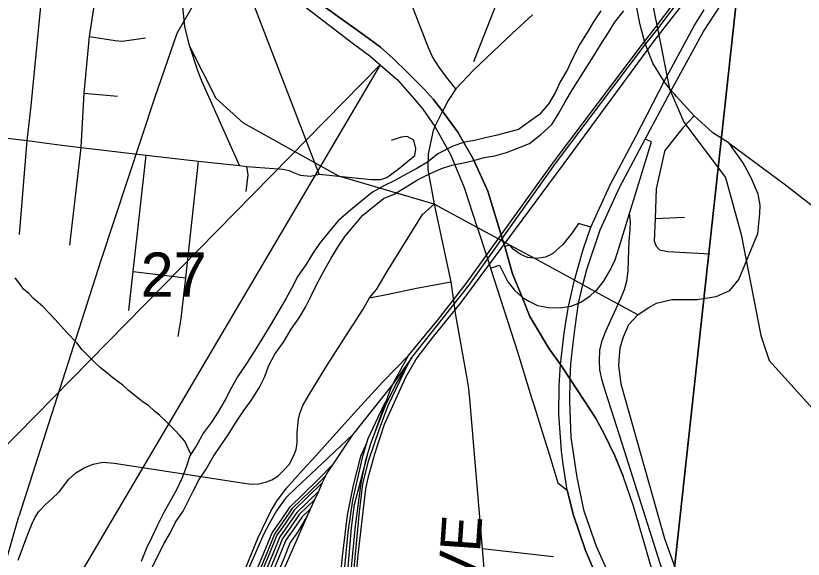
# Model space of a CAD drawing. Extents: x -8.2 to 38.5, y -0.1 to 21.9.
# Drawn here: x 5.137 to 5.881, y 17.376 to 17.89 of the extents above; entities that cross this region are included whole.
import ezdxf

# ---------------------------------------------------------------- set-up
doc = ezdxf.new("R2010")
doc.units = 0
for name, color, linetype in [('GM_X_Adjacent_County', 7, 'Continuous'), ('GM_X_Adjacent_County_Text', 7, 'Continuous'), ('GM_X_Airport_Location_Class_3', 7, 'Continuous'), ('GM_X_County_Road_Text', 7, 'Continuous'), ('GM_X_Interstate_Location', 7, 'Continuous'), ('GM_X_Major_Lake', 7, 'Continuous'), ('GM_X_Minor_River', 7, 'Continuous'), ('GM_X_State_Location', 7, 'Continuous'), ('GM_X_Township_Subdivision_Text', 7, 'Continuous'), ('GM_X_Township_Text', 7, 'Continuous'), ('GM_X_US_Location', 7, 'Continuous')]:
    doc.layers.add(name, color=color, linetype=linetype)

msp = doc.modelspace()

# ---------------------------------------------------------------- linework, layer by layer
at = {"layer": 'GM_X_Adjacent_County'}
msp.add_lwpolyline([(5.03564, 17.38985), (5.48132, 17.8434), (5.03564, 17.08755)], close=True, dxfattribs=at)
at = {"layer": 'GM_X_Adjacent_County_Text'}
msp.add_lwpolyline([(4.75441, 17.38985), (4.83948, 18.19258), (5.83799, 18.09248), (5.7325, 17.12325), (5.03564, 17.19219)], dxfattribs=at)
msp.add_lwpolyline([(6.85894, 17.99642), (6.75364, 16.98553), (5.7325, 17.12325), (5.83799, 18.09248)], close=True, dxfattribs=at)
at = {"layer": 'GM_X_Airport_Location_Class_3'}
for p, q in [((5.79156, 17.78276), (5.77757, 17.79539)), ((5.58243, 17.66065), (5.58539, 17.65149))]:
    msp.add_line(p, q, dxfattribs=at)
for points in [[(5.59883, 17.67204), (5.59746, 17.67656), (5.58298, 17.72409), (5.58161, 17.72708), (5.56894, 17.75479), (5.55447, 17.78002), (5.54008, 17.79971), (5.53161, 17.81077), (5.52289, 17.82015), (5.50709, 17.83638), (5.49339, 17.84965), (5.48154, 17.86018), (5.46608, 17.87148), (5.41629, 17.90733), (5.40533, 17.91556), (5.33437, 17.96919), (5.24763, 18.034), (5.20069, 18.07549)], [(5.7594, 17.81549), (5.75592, 17.81917), (5.74934, 17.82772), (5.7386, 17.84505), (5.73114, 17.86457), (5.72675, 17.88124), (5.72302, 17.90054), (5.71691, 17.97934), (5.70735, 18.05462), (5.70717, 18.05558)], [(5.29632, 17.98651), (5.32538, 17.96348), (5.39662, 17.90939), (5.45588, 17.86325), (5.47134, 17.85196), (5.48132, 17.8434), (5.488, 17.83765)], [(5.488, 17.83765), (5.49765, 17.82934), (5.51302, 17.8116), (5.52161, 17.80167), (5.53266, 17.78541), (5.54745, 17.75874), (5.56039, 17.7276), (5.57279, 17.68998), (5.5734, 17.68815)], [(5.77757, 17.79539), (5.76079, 17.81401), (5.7594, 17.81549)], [(5.7613, 17.36432), (5.74999, 17.39563), (5.70861, 17.5419), (5.70667, 17.55968), (5.70778, 17.57605), (5.71084, 17.58661), (5.71583, 17.59828), (5.72445, 17.60743), (5.73416, 17.61382), (5.74222, 17.61826), (5.75671, 17.62195), (5.78054, 17.62187), (5.79831, 17.62465), (5.81136, 17.63049), (5.81997, 17.64076), (5.8377, 17.68413), (5.83983, 17.70304), (5.84, 17.71109), (5.83819, 17.72128), (5.83161, 17.73674), (5.82355, 17.75137), (5.81077, 17.76939), (5.79545, 17.77926), (5.79156, 17.78276)], [(5.5734, 17.68815), (5.58035, 17.66706), (5.58243, 17.66065)], [(5.71065, 17.45498), (5.70279, 17.47416), (5.6926, 17.49495), (5.68444, 17.51017), (5.67396, 17.52647), (5.66069, 17.54665), (5.65141, 17.56047), (5.64067, 17.57538), (5.62246, 17.60587), (5.61538, 17.62419), (5.60624, 17.6462), (5.59883, 17.67204)], [(5.58539, 17.65149), (5.61084, 17.57231), (5.62422, 17.5291), (5.62654, 17.52152)], [(5.62654, 17.52152), (5.63003, 17.51013), (5.64231, 17.47065), (5.64889, 17.44872), (5.65771, 17.44158)], [(5.86706, 17.12546), (5.85953, 17.13966), (5.85133, 17.15452), (5.83903, 17.17436), (5.83173, 17.18557), (5.81998, 17.20364), (5.80911, 17.22051), (5.7981, 17.23732), (5.78865, 17.25173), (5.78168, 17.26126), (5.77559, 17.27082), (5.76723, 17.28754), (5.75788, 17.30456), (5.7488, 17.32855), (5.73932, 17.36131), (5.73052, 17.39223), (5.72048, 17.42654), (5.71065, 17.45498)], [(5.65771, 17.44158), (5.66359, 17.41823), (5.67499, 17.38468), (5.68513, 17.36098), (5.70146, 17.32687), (5.71759, 17.29913), (5.73996, 17.26601), (5.78093, 17.20921), (5.80478, 17.17521), (5.82506, 17.14461), (5.83932, 17.11884), (5.85193, 17.09208), (5.86158, 17.0684)]]:
    msp.add_lwpolyline(points, dxfattribs=at)
at = {"layer": 'GM_X_Interstate_Location'}
for points in [[(5.58539, 17.65149), (5.59373, 17.65434), (5.6018, 17.63841), (5.60814, 17.63079), (5.61538, 17.62419), (5.62166, 17.62017), (5.62981, 17.61611), (5.64024, 17.61435), (5.65129, 17.61397), (5.65899, 17.61519), (5.66156, 17.6156), (5.6685, 17.61846), (5.67073, 17.61938), (5.6794, 17.62527), (5.68402, 17.62944), (5.68601, 17.63123), (5.69206, 17.6387), (5.69743, 17.64792), (5.70268, 17.65824), (5.7071, 17.67225), (5.71648, 17.70292), (5.72408, 17.72777), (5.73728, 17.77065), (5.73131, 17.77337)], [(5.74791, 17.36544), (5.70961, 17.48582), (5.69383, 17.53501), (5.69094, 17.54527), (5.6887, 17.55526), (5.68817, 17.56394), (5.6887, 17.57394), (5.69081, 17.58301), (5.69423, 17.59196), (5.70882, 17.62379), (5.71185, 17.63128), (5.71422, 17.63917), (5.7154, 17.64878), (5.71579, 17.65956), (5.71645, 17.67679), (5.71711, 17.68771), (5.7175, 17.69586), (5.71648, 17.70292)], [(5.68016, 17.69017), (5.66845, 17.69361), (5.66261, 17.68482), (5.65366, 17.67367), (5.64402, 17.66511), (5.63719, 17.66193), (5.62885, 17.66047), (5.62653, 17.66074), (5.62016, 17.66146), (5.61324, 17.66456), (5.60684, 17.66929), (5.60348, 17.67329), (5.59883, 17.67204)]]:
    msp.add_lwpolyline(points, dxfattribs=at)
at = {"layer": 'GM_X_Minor_River'}
for points in [[(5.6895, 17.89451), (5.68276, 17.88406), (5.67679, 17.87398), (5.66966, 17.86316), (5.66323, 17.85005), (5.65799, 17.83918), (5.65122, 17.82759), (5.64677, 17.81784), (5.64041, 17.80701), (5.63177, 17.79661), (5.62172, 17.78967), (5.61165, 17.78236), (5.59027, 17.77687), (5.58072, 17.77447), (5.57041, 17.7721), (5.56089, 17.77046), (5.54978, 17.76659), (5.53555, 17.75938), (5.52585, 17.75168), (5.51582, 17.7455), (5.50581, 17.74008), (5.49503, 17.7343), (5.48465, 17.72927), (5.47386, 17.72311), (5.46223, 17.71393), (5.45136, 17.70474), (5.44164, 17.69627), (5.4334, 17.68625), (5.42397, 17.67473), (5.41726, 17.66505), (5.41089, 17.65459), (5.40339, 17.64379), (5.39737, 17.63218), (5.39217, 17.62245), (5.3858, 17.61161), (5.37824, 17.59891), (5.37188, 17.58845), (5.36433, 17.57613), (5.3556, 17.56232), (5.3465, 17.5489), (5.34011, 17.53731), (5.3349, 17.5272), (5.32812, 17.51561), (5.32178, 17.50591), (5.3143, 17.49587), (5.3079, 17.48389), (5.30156, 17.47419), (5.29825, 17.46441), (5.29375, 17.45276), (5.28851, 17.44152), (5.28291, 17.43142), (5.27732, 17.42132), (5.2709, 17.40859), (5.26565, 17.39734), (5.26043, 17.38685), (5.25553, 17.37446)], [(5.26599, 17.36885), (5.27161, 17.38009), (5.27685, 17.39096), (5.28282, 17.40105), (5.28804, 17.41153), (5.29516, 17.42197), (5.30481, 17.44145), (5.31041, 17.45193), (5.31675, 17.46163), (5.32352, 17.47321), (5.33065, 17.48403), (5.33816, 17.49483), (5.34491, 17.50566), (5.35243, 17.51684), (5.35952, 17.52652), (5.36706, 17.53847), (5.37229, 17.54895), (5.37559, 17.55873), (5.38161, 17.57034), (5.38988, 17.5815), (5.39705, 17.59384), (5.40456, 17.60464), (5.41053, 17.61473), (5.41614, 17.62521), (5.42177, 17.63683), (5.42818, 17.64918), (5.43495, 17.66076), (5.44132, 17.67122), (5.44805, 17.68167), (5.45668, 17.69168), (5.46453, 17.70134), (5.47462, 17.70942), (5.48431, 17.71713), (5.49429, 17.72141), (5.5047, 17.72758), (5.51628, 17.73485), (5.52705, 17.74025), (5.53896, 17.74562), (5.5489, 17.74877), (5.55844, 17.75078), (5.56835, 17.75279), (5.57944, 17.7559), (5.58934, 17.75753), (5.60043, 17.76064), (5.61193, 17.76526), (5.62228, 17.76915), (5.63275, 17.7776), (5.64326, 17.78718), (5.65001, 17.79801), (5.65599, 17.80848), (5.66276, 17.82006), (5.6695, 17.83051), (5.67704, 17.84245), (5.683, 17.85216), (5.68976, 17.86337), (5.69689, 17.87418), (5.70285, 17.88389), (5.71112, 17.89468)], [(5.30247, 17.47559), (5.29676, 17.48809), (5.29233, 17.49316), (5.28678, 17.49903), (5.27864, 17.50726), (5.27307, 17.51237), (5.26824, 17.51631), (5.2623, 17.5218), (5.25744, 17.52499), (5.2526, 17.52855), (5.24367, 17.53603), (5.2381, 17.54076), (5.23363, 17.54431), (5.22878, 17.54787), (5.22284, 17.55299), (5.21725, 17.55734), (5.21168, 17.56244), (5.20465, 17.5695), (5.19983, 17.5742), (5.19469, 17.58082), (5.18545, 17.5906), (5.17438, 17.60309), (5.16254, 17.61523), (5.15399, 17.6227), (5.14956, 17.6274), (5.14435, 17.63173), (5.14106, 17.63677), (5.13665, 17.64223)]]:
    msp.add_lwpolyline(points, dxfattribs=at)
at = {"layer": 'GM_X_State_Location'}
msp.add_line((5.58243, 17.66065), (5.58539, 17.65149), dxfattribs=at)
for points in [[(5.75024, 17.8086), (5.75592, 17.81917), (5.78641, 17.87488), (5.80242, 17.89944), (5.81712, 17.91896), (5.83159, 17.93563), (5.85287, 17.95603), (5.87655, 17.97467), (5.90112, 17.99134), (5.93014, 18.00732), (5.95069, 18.01393), (5.97986, 18.02205), (6.02021, 18.03038), (6.07943, 18.03937), (6.11343, 18.04551), (6.15049, 18.05582), (6.18339, 18.06635), (6.21761, 18.08017), (6.49366, 18.20681)], [(5.20069, 18.07549), (5.24763, 18.034), (5.33437, 17.96919), (5.40533, 17.91556), (5.41629, 17.90733), (5.46608, 17.87148), (5.48154, 17.86018), (5.49339, 17.84965), (5.50709, 17.83638), (5.52289, 17.82015), (5.53161, 17.81077), (5.54008, 17.79971), (5.55447, 17.78002), (5.56894, 17.75479), (5.58161, 17.72708), (5.58298, 17.72409), (5.59746, 17.67656), (5.59883, 17.67204)], [(5.29632, 17.98651), (5.32538, 17.96348), (5.39662, 17.90939), (5.45588, 17.86325), (5.47134, 17.85196), (5.48132, 17.8434), (5.488, 17.83765)], [(5.65771, 17.44158), (5.65351, 17.46844), (5.6524, 17.47899), (5.64999, 17.5132), (5.65021, 17.54018), (5.65141, 17.56047), (5.65459, 17.58756), (5.6564, 17.60038), (5.65899, 17.61519), (5.66459, 17.64002), (5.67275, 17.66899), (5.68016, 17.69017), (5.69836, 17.73031), (5.72244, 17.77597), (5.74934, 17.82772), (5.77758, 17.88024), (5.78712, 17.89559)], [(5.488, 17.83765), (5.49765, 17.82934), (5.51302, 17.8116), (5.52161, 17.80167), (5.53266, 17.78541), (5.54745, 17.75874), (5.56039, 17.7276), (5.57279, 17.68998), (5.5734, 17.68815)], [(5.66971, 17.44155), (5.66771, 17.45087), (5.66709, 17.45376), (5.66161, 17.49193), (5.6603, 17.52549), (5.66069, 17.54665), (5.66106, 17.56113), (5.66337, 17.58054), (5.6654, 17.59564), (5.6685, 17.61846), (5.6727, 17.6356), (5.67631, 17.65028), (5.68903, 17.68757), (5.70723, 17.72771), (5.73131, 17.77337), (5.75024, 17.8086)], [(5.5734, 17.68815), (5.58035, 17.66706), (5.58243, 17.66065)], [(5.59883, 17.67204), (5.60624, 17.6462), (5.61538, 17.62419), (5.62246, 17.60587), (5.64067, 17.57538), (5.65141, 17.56047), (5.66069, 17.54665), (5.67396, 17.52647), (5.68444, 17.51017), (5.6926, 17.49495), (5.70279, 17.47416), (5.71065, 17.45498)], [(5.58539, 17.65149), (5.61084, 17.57231), (5.62422, 17.5291), (5.62654, 17.52152)], [(5.62654, 17.52152), (5.63003, 17.51013), (5.64231, 17.47065), (5.64889, 17.44872), (5.65771, 17.44158)], [(5.86158, 17.0684), (5.85193, 17.09208), (5.83932, 17.11884), (5.82506, 17.14461), (5.80478, 17.17521), (5.78093, 17.20921), (5.73996, 17.26601), (5.71759, 17.29913), (5.70146, 17.32687), (5.68513, 17.36098), (5.67499, 17.38468), (5.66359, 17.41823), (5.65771, 17.44158)], [(5.73316, 17.29232), (5.72675, 17.30177), (5.70657, 17.34059), (5.69517, 17.36669), (5.6853, 17.3884), (5.67389, 17.42196), (5.66971, 17.44155)]]:
    msp.add_lwpolyline(points, dxfattribs=at)
at = {"layer": 'GM_X_Township_Subdivision_Text'}
for p, q in [((5.20177, 17.81669), (5.23318, 17.814)), ((5.74073, 17.69843), (5.76846, 17.6997)), ((5.24796, 17.64817), (5.29784, 17.64217)), ((5.57761, 17.38656), (5.64485, 17.37917))]:
    msp.add_line(p, q, dxfattribs=at)
for points in [[(5.14064, 17.68332), (5.14802, 17.77192), (5.15156, 17.80491), (5.1642, 17.93444), (5.17435, 18.03571), (5.17566, 18.05576)], [(5.18825, 17.67325), (5.19873, 17.76532), (5.20177, 17.81669), (5.20684, 17.87041), (5.21582, 17.9295), (5.22055, 17.98523), (5.22318, 18.01236), (5.22367, 18.01812), (5.22104, 18.0219), (5.21594, 18.02585)], [(5.42368, 17.74018), (5.41956, 17.75089), (5.35688, 17.91372)], [(5.20684, 17.87041), (5.23082, 17.86645), (5.23765, 17.86592), (5.25971, 17.8689)], [(5.34836, 17.74848), (5.31315, 17.8276), (5.30905, 17.83781), (5.30142, 17.86069)], [(5.77757, 17.79539), (5.7671, 17.78403), (5.75004, 17.76256), (5.74952, 17.76153), (5.74178, 17.72649), (5.74073, 17.69843), (5.73993, 17.67681), (5.74166, 17.67219), (5.74494, 17.66865), (5.75284, 17.66722), (5.79257, 17.66501)], [(5.12884, 17.77424), (5.14802, 17.77192), (5.16647, 17.76947), (5.18065, 17.76752), (5.19873, 17.76532), (5.26008, 17.75811), (5.30966, 17.75262), (5.34836, 17.74848), (5.35527, 17.74744), (5.3893, 17.74485), (5.39518, 17.74364), (5.39932, 17.74191), (5.40554, 17.73932), (5.41539, 17.73828), (5.42368, 17.74018), (5.44212, 17.7383), (5.47275, 17.73517), (5.48173, 17.73517), (5.48743, 17.73707), (5.49814, 17.74502), (5.51404, 17.7578), (5.51473, 17.76437), (5.513, 17.77232), (5.50678, 17.77577), (5.50091, 17.77508), (5.49158, 17.77197)], [(5.24391, 17.61137), (5.24796, 17.64817), (5.26008, 17.75811)], [(5.29039, 17.58702), (5.29337, 17.60379), (5.29784, 17.64217), (5.30966, 17.75262)], [(5.35475, 17.72394), (5.35665, 17.73967), (5.35527, 17.74744)], [(5.13952, 17.37557), (5.14854, 17.40025), (5.15249, 17.41038), (5.1555, 17.41607), (5.15898, 17.42145), (5.16562, 17.42841), (5.17084, 17.43316), (5.17844, 17.44044), (5.18714, 17.45215), (5.19394, 17.458), (5.20169, 17.46274), (5.21008, 17.46622), (5.21941, 17.46812), (5.22986, 17.46717), (5.35072, 17.44866), (5.35942, 17.4474), (5.36638, 17.44772), (5.37382, 17.44961), (5.37888, 17.45135), (5.38474, 17.45531), (5.39027, 17.46053), (5.39534, 17.46607), (5.39929, 17.47398), (5.40182, 17.48015), (5.40277, 17.48648), (5.40293, 17.49644), (5.40404, 17.50878), (5.4053, 17.51416), (5.40815, 17.52175), (5.41369, 17.53141), (5.42967, 17.55735), (5.45118, 17.59121), (5.45593, 17.59864), (5.46526, 17.61272), (5.47101, 17.62326), (5.47775, 17.63127), (5.48787, 17.64814), (5.52119, 17.70212), (5.53225, 17.71205)], [(5.47101, 17.62326), (5.48863, 17.62689), (5.51545, 17.63248), (5.548, 17.63851)]]:
    msp.add_lwpolyline(points, dxfattribs=at)
at = {"layer": 'GM_X_Township_Text'}
for points in [[(5.72445, 17.60743), (5.68402, 17.62944), (5.6727, 17.6356), (5.66459, 17.64002), (5.62653, 17.66074), (5.60348, 17.67329), (5.59746, 17.67656), (5.57279, 17.68998), (5.53225, 17.71205), (5.44212, 17.7383), (5.41956, 17.75089), (5.35227, 17.78843), (5.3263, 17.81159), (5.30142, 17.86069), (5.2966, 17.87943), (5.295, 17.8987), (5.29371, 17.92079)], [(5.55262, 17.8207), (5.54381, 17.83175), (5.53679, 17.84132), (5.53052, 17.85117), (5.52678, 17.85954), (5.50378, 17.91914)], [(5.62496, 17.89079), (5.60589, 17.87303), (5.56939, 17.83851), (5.55262, 17.8207), (5.54478, 17.80876), (5.54243, 17.80424)], [(5.54243, 17.80424), (5.54008, 17.79971), (5.53266, 17.78541), (5.53124, 17.78141), (5.52867, 17.76988), (5.52664, 17.75921), (5.52617, 17.74462), (5.53225, 17.71205), (5.548, 17.63851), (5.55229, 17.60703), (5.56265, 17.54916), (5.56462, 17.53782), (5.56594, 17.52417), (5.57761, 17.38656), (5.58024, 17.35237)], [(5.81077, 17.76939), (5.86272, 17.73108), (5.9005, 17.70188), (5.90674, 17.69597), (5.91303, 17.68867), (5.92253, 17.67591), (5.92762, 17.66868), (5.93329, 17.65898), (5.93831, 17.64977), (5.94604, 17.63251), (5.95689, 17.60982), (5.98632, 17.54356), (6.00769, 17.49342), (6.03104, 17.44065), (6.05095, 17.39824)]]:
    msp.add_lwpolyline(points, dxfattribs=at)
at = {"layer": 'GM_X_US_Location'}
for p, q in [((5.69953, 18.09843), (5.743, 17.87792)), ((5.45497, 17.49386), (5.43602, 17.4655)), ((5.42977, 17.45546), (5.42657, 17.44858)), ((5.42657, 17.44858), (5.42285, 17.44058)), ((5.42285, 17.44058), (5.41917, 17.43265)), ((5.41917, 17.43265), (5.41511, 17.42392))]:
    msp.add_line(p, q, dxfattribs=at)
for points in [[(5.70055, 18.21721), (5.65914, 18.1997), (5.57835, 18.16166), (5.51066, 18.12721), (5.44065, 18.07343), (5.37877, 18.01424), (5.33689, 17.9566), (5.28911, 17.87309), (5.26824, 17.81194), (5.21734, 17.65871), (5.14005, 17.41698)], [(5.69953, 18.09843), (5.63364, 18.00993), (5.56924, 17.84642)], [(5.80729, 17.95304), (5.74005, 17.8664), (5.65916, 17.75641), (5.55739, 17.61913), (5.53027, 17.58576), (5.5158, 17.56669), (5.50511, 17.54827), (5.48506, 17.50388), (5.47569, 17.47577), (5.46944, 17.45292), (5.4673, 17.44306), (5.46007, 17.38075), (5.45004, 17.26665)], [(5.47686, 17.49769), (5.49184, 17.5393), (5.49587, 17.54728), (5.50806, 17.56905), (5.53626, 17.60335), (5.5624, 17.63695), (5.64483, 17.75167), (5.72895, 17.86319), (5.74126, 17.87891), (5.77634, 17.92567)], [(5.5077, 17.56121), (5.51107, 17.56696), (5.56499, 17.63509), (5.64682, 17.75018), (5.73092, 17.86167), (5.74324, 17.8774), (5.77832, 17.92417)], [(5.743, 17.87792), (5.75427, 17.82078), (5.76796, 17.78951), (5.8073, 17.73702), (5.82221, 17.68332), (5.84047, 17.58778), (5.84859, 17.56427), (5.89244, 17.51546), (5.90911, 17.50192), (5.92954, 17.49135), (5.94311, 17.47801), (5.95275, 17.45915), (5.96194, 17.43282), (5.96616, 17.40644), (5.98566, 17.34082)], [(5.35111, 17.36077), (5.36592, 17.39691), (5.37785, 17.42196), (5.38367, 17.43138), (5.39286, 17.44351), (5.40844, 17.46139), (5.42012, 17.47397), (5.45332, 17.51061), (5.48348, 17.54368), (5.50806, 17.56905)], [(5.51107, 17.56696), (5.4929, 17.5414), (5.45497, 17.49386)], [(5.4596, 16.65269), (5.43146, 16.6891), (5.42176, 16.70751), (5.41288, 16.73053), (5.41075, 16.73727), (5.4068, 16.757), (5.4045, 16.77607), (5.4045, 16.80434), (5.40598, 16.83459), (5.4137, 16.91219), (5.42686, 17.05079), (5.43919, 17.1856), (5.45218, 17.32107), (5.46155, 17.42135), (5.46483, 17.44782), (5.47059, 17.47002), (5.48045, 17.49977), (5.48884, 17.5218), (5.5077, 17.56121)], [(5.43874, 17.20915), (5.45791, 17.40795), (5.46312, 17.44821), (5.46777, 17.47011), (5.47243, 17.48572), (5.47825, 17.50144), (5.48609, 17.52158), (5.49577, 17.5408), (5.49956, 17.54734), (5.5077, 17.56121)], [(5.48634, 17.52546), (5.47888, 17.51042), (5.46951, 17.4902), (5.46831, 17.48623)], [(5.45497, 17.49386), (5.43853, 17.4784), (5.42719, 17.46755), (5.41617, 17.45703), (5.40253, 17.44453), (5.392, 17.43434), (5.38345, 17.42218), (5.37655, 17.4105), (5.37145, 17.40047), (5.35123, 17.35444), (5.27972, 17.18297), (5.25752, 17.12641), (5.25357, 17.11375), (5.24963, 17.09583), (5.24634, 17.07282), (5.24223, 17.04848), (5.24108, 17.03024), (5.23977, 17.01448)], [(5.46831, 17.48623), (5.46264, 17.47341), (5.45557, 17.44645), (5.44998, 17.41801), (5.44538, 17.37904), (5.4434, 17.35948), (5.43929, 17.34189), (5.4359, 17.33305)], [(5.46831, 17.48623), (5.46408, 17.4722), (5.45521, 17.43225), (5.45052, 17.40192), (5.44559, 17.34939)], [(5.39347, 16.80809), (5.39651, 16.82264), (5.40169, 16.84755), (5.40613, 16.89366), (5.41748, 17.01031), (5.42487, 17.09465), (5.44164, 17.27294), (5.4488, 17.34273), (5.45422, 17.40611), (5.45693, 17.4283), (5.46915, 17.47473)], [(5.31835, 17.25531), (5.37178, 17.38305), (5.37918, 17.40146), (5.38756, 17.41346), (5.39628, 17.42596), (5.42242, 17.45144), (5.43602, 17.4655)], [(5.43602, 17.4655), (5.4308, 17.45769), (5.42977, 17.45546)], [(5.42977, 17.45546), (5.42418, 17.44969), (5.39818, 17.42434), (5.3896, 17.41204), (5.38138, 17.40027), (5.37408, 17.3821), (5.32064, 17.25434)], [(5.42657, 17.44858), (5.42594, 17.44793), (5.40009, 17.42273), (5.39164, 17.41062), (5.38358, 17.39908), (5.37638, 17.38116), (5.32293, 17.25338), (5.27713, 17.14438), (5.27067, 17.12531), (5.26318, 17.09683), (5.25848, 17.0743), (5.25541, 17.04942), (5.2546, 17.02234), (5.25525, 16.99828), (5.25801, 16.9634), (5.26514, 16.93084), (5.28202, 16.87184), (5.30403, 16.79971), (5.32115, 16.74532), (5.34153, 16.67907), (5.34835, 16.66049)], [(5.42285, 17.44058), (5.40247, 17.42071), (5.39419, 17.40884), (5.38633, 17.39759), (5.37926, 17.37998), (5.3258, 17.25218), (5.28004, 17.14328), (5.27365, 17.12441), (5.26621, 17.09612), (5.26155, 17.0738), (5.25851, 17.04918), (5.25771, 17.02233), (5.25836, 16.99844), (5.26109, 16.96385), (5.26815, 16.9316), (5.285, 16.87272), (5.30701, 16.80062)], [(5.41917, 17.43265), (5.40485, 17.41869), (5.39674, 17.40706), (5.38908, 17.3961), (5.38213, 17.3788), (5.32867, 17.25098), (5.28295, 17.14217), (5.27662, 17.12352), (5.26923, 17.0954), (5.26462, 17.07329), (5.26162, 17.04895), (5.26082, 17.02233), (5.26146, 16.9986), (5.26417, 16.96431), (5.27117, 16.93236), (5.28798, 16.87361), (5.30998, 16.80153), (5.31999, 16.77837), (5.33627, 16.74927), (5.37244, 16.67989), (5.37705, 16.67032)], [(5.41511, 17.42392), (5.40746, 17.41647), (5.39954, 17.4051), (5.39211, 17.39447), (5.38529, 17.37751), (5.33182, 17.24966), (5.28614, 17.14096), (5.2799, 17.12254), (5.27256, 17.09462), (5.26799, 17.07273), (5.26503, 17.04868), (5.26424, 17.02232), (5.26487, 16.99879), (5.26756, 16.96481), (5.27448, 16.93319), (5.29125, 16.87457), (5.30962, 16.8144), (5.31884, 16.79316), (5.33183, 16.77212), (5.34613, 16.74878), (5.35256, 16.73937)], [(5.41511, 17.42392), (5.41496, 17.4236), (5.41259, 17.41821)], [(5.11958, 17.34637), (5.14005, 17.41698)], [(5.41259, 17.41821), (5.40336, 17.40244), (5.39623, 17.39224), (5.3896, 17.37574), (5.33611, 17.24786), (5.2905, 17.13931), (5.28436, 17.12119), (5.2771, 17.09355), (5.27259, 17.07197), (5.26968, 17.04833), (5.2689, 17.02232), (5.26953, 16.99903), (5.27218, 16.9655), (5.279, 16.93433), (5.2943, 16.88085), (5.30646, 16.85454)], [(5.41259, 17.41821), (5.38034, 17.34478), (5.30942, 17.17547), (5.29398, 17.13806), (5.28627, 17.11521), (5.28033, 17.09027), (5.27617, 17.06801), (5.2736, 17.04633), (5.27231, 17.0214), (5.27499, 16.97747), (5.28033, 16.94303), (5.28597, 16.91483), (5.29577, 16.88425)]]:
    msp.add_lwpolyline(points, dxfattribs=at)

# ---------------------------------------------------------------- texts
at = {"layer": 'GM_X_County_Road_Text'}
msp.add_text('27', height=0.041856, rotation=0.00001, dxfattribs=at).set_placement((5.25505, 17.62439))
at = {"layer": 'GM_X_Major_Lake'}
msp.add_text('AVE', height=0.037879, rotation=86.05688, dxfattribs=at).set_placement((5.57077, 17.31523))

doc.saveas('drawing.dxf')
